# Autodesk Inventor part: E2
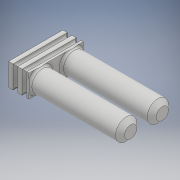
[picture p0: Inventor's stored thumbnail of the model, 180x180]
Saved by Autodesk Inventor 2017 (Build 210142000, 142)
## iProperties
Part Number: E2
Material: Genérico
Document SubType Name: Modeling
Designer: Diego
Density: 1 g/cm^3
Appearance: Valor por defecto
Author: Diego
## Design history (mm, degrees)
derived "Lubina.ipt"
fillet "Empalme1" dims "d1" = 0.5
feature "Sólido20::Lubina.ipt" dims "d0" = 10
tag "OperaciónIdentificador1"
node "Sólido1"
